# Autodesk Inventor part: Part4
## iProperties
Created: 2002-02
Part Number: Part4
Document SubType Name: ﾓﾃﾞﾘﾝｸﾞ
Designer: Administrator
Control State: 0
Master: False
Checked Out: False
Shininess: 64.0
Length Units: 11269
Angle Units: 11279
Time Units: 11290
Mass Units: 11284
Length Display Precision: 2
Angle Display Precision: 1
Density: 0.0
Volumn: 0.0
Area: 0.0
PropertySet Name: Model Information
Author: Administrator
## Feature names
1. 押し出し1 [Extrusion]
2. 押し出し2 [Extrusion]
3. 押し出し3 [Extrusion]
4. 押し出し4 [Extrusion]
